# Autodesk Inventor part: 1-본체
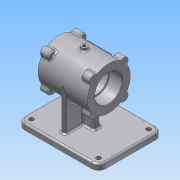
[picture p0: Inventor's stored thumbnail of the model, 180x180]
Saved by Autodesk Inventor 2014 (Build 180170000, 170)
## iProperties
Created: 2016-01
Part Number: 1-본체
Material: 알루미늄 6061
Document SubType Name: Modeling
Designer: Administrator
Density: 2.71 g/cm^3
Appearance: 알루미늄 - 평지
Mass: 1058.22 g
Surface Area: 835.9 cm^2
Volume: 390.486 cm^3
Author: Administrator
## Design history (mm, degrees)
sketch "스케치1"
  geometry: L1 (70, -55)-(-70, -55); L2 (-70, -55)-(-70, 55); L3 (-70, 55)-(70, 55); L4 (70, 55)-(70, -55); L5 (70, -55)-(-70, 55); L6 (-70, -55)-(70, 55); 1 further point
  constraints: 12 end point, 2 midpoint, 2 parallel, 1 horizontal, 1 perpendicular
  dimensions: "d0" = 140 distance of L2.end L3.end; "d1" = 110 distance of L3.end L1.start
extrude "돌출1" new body sketch "스케치1" distance "d2" = 10; taper "d3" = 0 deg
node "작업 평면6"
sketch "스케치7"
  geometry: L1 (0, 0)-(-110, 0) reference; C1 r 37 at (-55, 80); 2 further points
  constraints: 1 centre point, 1 midpoint, 1 vertical alignment
  dimensions: "d17" = 74 diameter of C1; "d18" = 80 distance from line of C1.centre L1
extrude "돌출4" join sketch "스케치7" stored distance "d19" = 85; taper "d20" = 0 deg
node "작업 평면7"
sketch "스케치8"
  geometry: L1 (-70, 55)-(-70, -55) reference; L2 (0, 37)-(-70, 37); L3 (0, -37)-(-70, -37); A1 r 37 centre (0, 0) between (0, 37) and (0, -37) reference; 1 further point
  constraints: 4 end point, 2 perpendicular, 2 point on circle, 2 point on line, 2 tangent
extrude "돌출5" join sketch "스케치8" stored distance "d21" = 8; taper "d22" = 0 deg
node "작업 평면8"
sketch "스케치9"
  geometry: L1 (-32.5, 43)-(52.5, 43) reference; L2 (-13, 10)-(0.341, 94.231); L3 (0.341, 94.231)-(23.659, 94.231); L4 (23.659, 94.231)-(37, 10); L5 (6, 80)-(14, 80) reference; L6 (14, 10)-(14, 80) reference; L7 (6, 10)-(14, 10) reference; L8 (6, 80)-(6, 10) reference; L9 (70, 10)-(-70, 10) reference; L10 (-13, 10)-(37, 10); 2 further points
  constraints: 8 end point, 2 point on line, 1 equal length, 1 horizontal
  dimensions: "d25" = 99 deg angle of L2 L9; "d26" = 50 distance of L4.end L2.start; "d27" = 6 distance from line of point (12, 10) L8; "d28" = 25 distance of point (12, 10) L2.start; "d30" = 25 distance of L4.end point (12, 10); "d31" = 84.23098 vertical distance of L4.end L3.end
extrude "돌출6" join sketch "스케치9" stored distance "d32" = 12; taper "d33" = 0 deg
sketch "스케치10"
  geometry: L1 (0, 0)-(37, 0); L2 (0, 0)-(26.163, 26.163); L3 (0, 0)-(-26.163, 26.163); L4 (0, 0)-(-26.163, -26.163); L5 (0, 0)-(26.163, -26.163); L6 (0, 0)-(-37, 0); A1 r 7 centre (26.163, 26.163) between (30.622, 20.767) and (20.767, 30.622); A2 r 7 centre (26.163, -26.163) between (20.767, -30.622) and (30.622, -20.767); A3 r 7 centre (-26.163, -26.163) between (-30.622, -20.767) and (-20.767, -30.622); A4 r 7 centre (-26.163, 26.163) between (-20.767, 30.622) and (-30.622, 20.767); 1 further point
  constraints: 12 end point, 8 point on circle, 4 centre point, 4 coincident, 3 equal radius, 1 collinear, 1 horizontal, 1 perpendicular, 15 other
  dimensions: "d34" = 45 deg angle of L1 L2; "d35" = 90 deg angle of L5 L2; "d36" = 45 deg angle of L6 L3; "d37" = 14 diameter of A2
extrude "돌출7" join sketch "스케치10" distance "d38" = 15; taper "d39" = 0 deg
sketch "스케치11"
  geometry: A1 r 7 centre (106.163, 28.837) between (100.767, 24.378) and (110.622, 34.233) reference; A2 r 7 centre (106.163, 81.163) between (110.622, 75.767) and (100.767, 85.622) reference; A3 r 7 centre (53.837, 81.163) between (59.233, 85.622) and (49.378, 75.767) reference; A4 r 7 centre (53.837, 28.837) between (49.378, 34.233) and (59.233, 24.378) reference; 5 further points
  constraints: 4 coincident
hole "구멍1" sketch "스케치11" at (106.163, 81.163), (106.163, 28.837), (53.837, 28.837), (53.837, 81.163) diameter "d40" = 3.242; stored, may be unused: countersink angle "d44" = 90 deg, drill point angle "d46" = 118 deg; dims "d41" = 9, "d42" = 4, "d43" = 2, "d45" = 11
hole "구멍2" diameter "d49" = 47; stored, may be unused: countersink angle "d53" = 90 deg, drill point angle "d55" = 0 deg; dims "d47" = 10, "d48" = 10, "d50" = 6, "d51" = 4, "d52" = 2, "d54" = 22
hole "구멍3" diameter "d58" = 42; stored, may be unused: countersink angle "d62" = 90 deg, drill point angle "d64" = 0 deg; dims "d56" = 10, "d57" = 10, "d59" = 6, "d60" = 4, "d61" = 2, "d63" = 41
node "작업 평면9"
node "작업 평면11"
sketch "스케치13"
  geometry: L1 (-52.5, 20.767)-(-52.5, -20.767) reference; C1 r 5 at (-10, 0); 2 further points
  constraints: 1 centre point, 1 horizontal alignment, 1 midpoint
  dimensions: "d66" = 42.5 distance from line of C1.centre L1; "d67" = 10 diameter of C1
extrude "돌출8" join sketch "스케치13" stored distance "d68" = 15; taper "d69" = 0 deg
sketch "스케치15"
  geometry: L1 (-70, -55)-(70, -55) reference; L2 (70, 55)-(-70, 55) reference; L3 (-70, 55)-(-70, -55) reference; L4 (-6, 37)-(-6, 6) reference; L5 (-58, 43)-(-58, -43); 3 further points
  constraints: 2 coincident, 2 end point, 1 parallel
  dimensions: "d72" = 12 distance from line of L5.start L3; "d73" = 12 distance from line of L5.start L2; "d74" = 12 distance from line of L5.end L1
hole "구멍4" sketch "스케치15" at (-58, 43), (-58, -43) diameter "d75" = 8; stored, may be unused: countersink angle "d79" = 90 deg, drill point angle "d81" = 0 deg; dims "d76" = 6, "d77" = 4, "d78" = 2, "d80" = 41
node "작업 평면12"
sketch "스케치16"
  geometry: L1 (55, -40)-(-55, -40); L2 (-55, -40)-(-55, 40); L3 (-55, 40)-(55, 40); L4 (55, 40)-(55, -40); L5 (55, -40)-(-55, 40); L6 (-55, -40)-(55, 40); C1 r 4 at (-58, 43) reference; C2 r 4 at (-58, -43) reference; C3 r 4 at (58, 43) reference; C4 r 4 at (58, -43) reference; A1 r 20 centre (-58, 43) between (-55, 23.226) and (-38.226, 40); A2 r 20 centre (-58, -43) between (-38.226, -40) and (-55, -23.226); A3 r 20 centre (58, -43) between (55, -23.226) and (38.226, -40); A4 r 20 centre (58, 43) between (38.226, 40) and (55, 23.226); 1 further point
  constraints: 12 end point, 8 point on circle, 8 point on line, 4 centre point, 4 coincident, 3 equal radius, 2 midpoint, 2 parallel, 1 horizontal, 1 perpendicular
  dimensions: "d82" = 110 distance of L2.end L3.end; "d83" = 80 distance of L1.end L2.end; "d84" = 40 diameter of A1
extrude "돌출9" cut sketch "스케치16" distance "d85" = 5; taper "d86" = 0 deg
node "작업 평면13"
sketch "스케치17"
  geometry: L1 (80, 55)-(80, 78.5); L2 (80, 55)-(135.083, 110.083); 1 further point
  constraints: 4 end point, 1 vertical, 1 vertical alignment, 1 other
  dimensions: "d87" = 45 deg angle of L2 L1
node "작업 평면14"
sketch "스케치19"
  geometry: 3 further points
  constraints: 1 coincident, 1 other
feature "엠보싱1" sketch "스케치19" dims "d88" = 0.5, "d89" = 0
hole "구멍5" diameter "d92" = 5.188; stored, may be unused: countersink angle "d96" = 90 deg, drill point angle "d98" = 0 deg; dims "d93" = 6, "d94" = 4, "d95" = 2, "d97" = 41, "d109" = 10, "d110" = 10
chamfer "모따기1" distance "d99" = 1; stored, may be unused: second distance "d100" = 2, angle "d101" = 45 deg
fillet "모깎기1" dims "d102" = 0.3
fillet "모깎기2" dims "d103" = 3
fillet "모깎기3" dims "d104" = 3
fillet "모깎기4" dims "d105" = 3
fillet "모깎기5" dims "d106" = 3
fillet "모깎기6" dims "d107" = 12
fillet "모깎기7" dims "d108" = 3
fillet "모깎기8" dims "d111" = 3
fillet "모깎기9" dims "d112" = 3
fillet "모깎기10" dims "d113" = 1
node "솔리드1"
mirror "대칭1"
mirror "대칭2"
node "투영된 루프1"
node "투영된 루프2"
other parameters: "d23" = 0, "d65" = 122
